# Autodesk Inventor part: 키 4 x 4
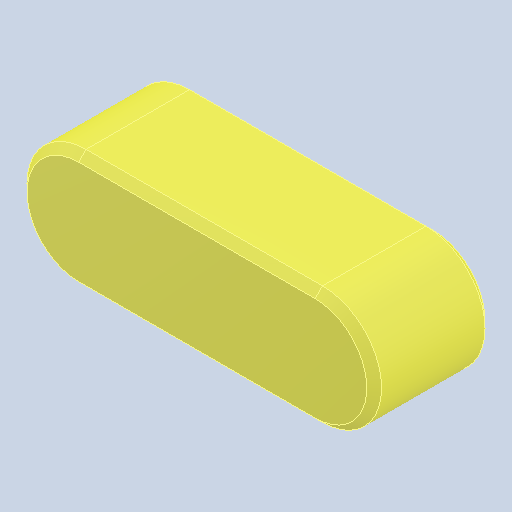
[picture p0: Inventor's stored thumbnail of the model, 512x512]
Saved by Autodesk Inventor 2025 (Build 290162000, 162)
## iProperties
Created: 2024-08
Part Number: 키 4 x 4
Material: 강철, 연강
Description: 키 및 해당 키홈
Document SubType Name: Modeling
Designer: SAMSUNG
Density: 7.86 g/cm^3
Appearance: 기본값
Author: jhkim
Sending System: Autodesk Inventor 2025
Preprocessor: ST-DEVELOPER v20
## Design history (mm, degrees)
feature "Solid1"
node "솔리드1"
